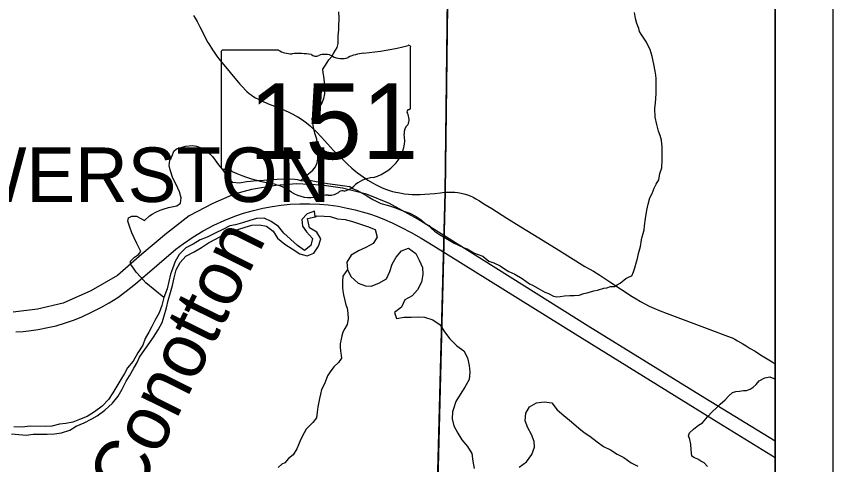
# Model space of a CAD drawing. Extents: x -1.2 to 34, y -8.5 to 22.
# Drawn here: x 7.582 to 9, y 16.749 to 17.528 of the extents above; entities that cross this region are included whole.
import ezdxf

# ---------------------------------------------------------------- set-up
doc = ezdxf.new("R2010")
doc.units = 0
for name, color, linetype in [('GM_X_Corporation_Text', 7, 'Continuous'), ('GM_X_Major_River', 7, 'Continuous'), ('GM_X_Major_River_Text', 7, 'Continuous'), ('GM_X_Minor_River', 7, 'Continuous'), ('GM_X_Rail_Line', 7, 'Continuous'), ('GM_X_State_Location', 7, 'Continuous'), ('GM_X_State_Route', 7, 'Continuous'), ('GM_X_State_Shield', 7, 'Continuous'), ('GM_X_Unincorporated_Text', 7, 'Continuous'), ('SH_Cut_Line', 7, 'Continuous'), ('SH_Data', 7, 'Continuous')]:
    doc.layers.add(name, color=color, linetype=linetype)

msp = doc.modelspace()

# ---------------------------------------------------------------- linework, layer by layer
at = {"layer": 'GM_X_Major_River'}
for points in [[(7.5731, 16.8023), (7.5861, 16.801), (7.5986, 16.8), (7.6107, 16.8013), (7.6233, 16.8018), (7.6354, 16.8016), (7.6479, 16.8021), (7.6604, 16.8041), (7.6744, 16.8085), (7.6857, 16.8154), (7.6993, 16.8213), (7.7126, 16.8283), (7.7224, 16.8337), (7.7352, 16.843), (7.7487, 16.8553), (7.7588, 16.8676), (7.7655, 16.8798), (7.7725, 16.8935), (7.7781, 16.9031), (7.7859, 16.9161), (7.7915, 16.926), (7.7959, 16.9355), (7.8049, 16.9489), (7.8135, 16.9608), (7.8198, 16.9704), (7.828, 16.983), (7.8351, 16.9956), (7.8384, 17.0074), (7.8424, 17.0211), (7.8452, 17.034), (7.8493, 17.0477), (7.8529, 17.0599), (7.8562, 17.0733), (7.8594, 17.087), (7.8661, 17.0999), (7.8762, 17.1111), (7.8906, 17.1185), (7.9034, 17.1258), (7.9154, 17.1339), (7.9279, 17.1405), (7.9418, 17.1483), (7.9535, 17.1537), (7.9664, 17.1573), (7.9793, 17.1616), (7.991, 17.1648), (8.0043, 17.1654), (8.0165, 17.1632), (8.028, 17.1546), (8.0357, 17.1422), (8.0484, 17.1317), (8.061, 17.1239), (8.074, 17.115), (8.087, 17.1117), (8.0983, 17.1164), (8.1065, 17.1283), (8.1109, 17.1412), (8.1035, 17.1529), (8.0909, 17.1603), (8.0876, 17.1766)], [(8.1009, 17.1794), (8.0997, 17.1893), (8.0868, 17.1846), (8.0779, 17.1749), (8.079, 17.1634), (8.0857, 17.1531), (8.0965, 17.1418), (8.0936, 17.1293), (8.0823, 17.1208), (8.0704, 17.1294), (8.0466, 17.1511), (8.037, 17.1623), (8.0247, 17.1713), (8.0121, 17.1772), (7.9992, 17.1763), (7.9875, 17.1731), (7.9746, 17.1688), (7.9625, 17.1652), (7.9527, 17.1636), (7.9402, 17.1574), (7.9274, 17.1508), (7.913, 17.1438), (7.9013, 17.1391), (7.8889, 17.1321), (7.876, 17.1255), (7.8648, 17.114), (7.8577, 17.1017), (7.8529, 17.0892), (7.8493, 17.0796), (7.8467, 17.0671), (7.8435, 17.0541), (7.838, 17.0389), (7.8347, 17.0252), (7.8299, 17.0126), (7.8225, 16.9992), (7.8169, 16.9885), (7.8121, 16.9786), (7.8054, 16.9679), (7.8014, 16.9561), (7.7928, 16.9427), (7.7846, 16.9286), (7.7749, 16.9167), (7.7697, 16.9068), (7.763, 16.8968), (7.7563, 16.885), (7.7496, 16.8735), (7.7421, 16.8617), (7.7309, 16.8501), (7.7177, 16.8405), (7.7045, 16.8324), (7.6913, 16.8269), (7.6796, 16.8222), (7.6678, 16.8202), (7.6565, 16.8189), (7.6432, 16.8157), (7.6315, 16.8148), (7.6056, 16.8152), (7.592, 16.8136), (7.5775, 16.8141)], [(8.0876, 17.1766), (8.1009, 17.1794)], [(8.1009, 17.1794), (8.1036, 17.181), (8.1165, 17.1804), (8.1268, 17.1801), (8.1397, 17.1761), (8.153, 17.1748), (8.166, 17.1711), (8.1778, 17.1671), (8.1919, 17.1627), (8.2049, 17.1572), (8.2088, 17.1439), (8.2014, 17.1332), (8.1889, 17.1259), (8.1761, 17.12), (8.1636, 17.113), (8.1558, 17.1004), (8.1571, 17.0879), (8.163, 17.0754), (8.1756, 17.0642), (8.1886, 17.0594), (8.1981, 17.0588), (8.2117, 17.0639), (8.2249, 17.0713), (8.2304, 17.0842), (8.2345, 17.0968), (8.2419, 17.109), (8.2509, 17.1202), (8.263, 17.1249), (8.2756, 17.1159), (8.2815, 17.1038), (8.2873, 17.091), (8.2878, 17.0792), (8.2854, 17.0656), (8.2787, 17.0526), (8.2697, 17.0418), (8.2569, 17.0352), (8.2506, 17.0226), (8.2385, 17.013), (8.2421, 17.0024), (8.2557, 17.0049), (8.2675, 17.005), (8.2811, 17.0055), (8.291, 17.0049), (8.3051, 17.0005), (8.3178, 16.9916), (8.3255, 16.9795), (8.3351, 16.9671), (8.3471, 16.9551), (8.3589, 16.9462), (8.3655, 16.9345), (8.3687, 16.9212), (8.3696, 16.9091), (8.3687, 16.8966), (8.3612, 16.8832), (8.353, 16.8706), (8.3452, 16.8583), (8.3412, 16.8454)], [(8.4556, 16.744), (8.468, 16.7536), (8.4773, 16.7662), (8.4821, 16.7792), (8.4816, 16.7887), (8.4769, 16.8007), (8.4703, 16.8128), (8.466, 16.8245), (8.467, 16.8378), (8.4733, 16.8493), (8.4857, 16.8563), (8.4986, 16.8579), (8.5119, 16.8558), (8.5212, 16.8438), (8.5327, 16.8341), (8.5461, 16.8232), (8.5588, 16.812), (8.5684, 16.8045), (8.5779, 16.7982), (8.591, 16.7881), (8.6021, 16.7799), (8.6139, 16.7743), (8.6258, 16.7669), (8.6373, 16.761), (8.6499, 16.752), (8.6614, 16.7457)], [(8.3412, 16.8454), (8.3397, 16.8404), (8.3387, 16.8283), (8.3419, 16.8162), (8.3489, 16.8034), (8.3555, 16.7917), (8.3655, 16.78), (8.3729, 16.768), (8.3746, 16.7544), (8.3774, 16.7419)]]:
    msp.add_lwpolyline(points, dxfattribs=at)
at = {"layer": 'GM_X_Minor_River'}
for points in [[(8.0755, 17.2425), (8.0968, 17.2604), (8.1017, 17.2665), (8.1042, 17.2734), (8.1057, 17.2803), (8.1054, 17.2982), (8.1045, 17.3092), (8.1037, 17.3146), (8.1021, 17.3195), (8.1005, 17.3248), (8.0977, 17.3354), (8.096, 17.3445), (8.0956, 17.3502), (8.0978, 17.3556), (8.1011, 17.3606), (8.1089, 17.3714), (8.1126, 17.3764), (8.1159, 17.3852), (8.1177, 17.3932), (8.1183, 17.4032), (8.117, 17.4134), (8.1157, 17.4241), (8.1149, 17.4294), (8.1144, 17.4359), (8.1174, 17.4412), (8.1218, 17.4474), (8.1248, 17.4524), (8.1296, 17.4582), (8.1333, 17.4643), (8.1389, 17.4739), (8.1407, 17.4804), (8.1406, 17.4888), (8.1409, 17.4938), (8.1418, 17.5044), (8.1418, 17.5102), (8.1423, 17.525), (8.1422, 17.5357)], [(8.3085, 17.1546), (8.3169, 17.1487), (8.328, 17.1424), (8.3425, 17.1338), (8.3486, 17.1309), (8.36, 17.1253), (8.365, 17.1235), (8.3764, 17.1168), (8.3821, 17.1146), (8.3924, 17.111), (8.4027, 17.1024), (8.4115, 17.0995), (8.4222, 17.0939), (8.4317, 17.088), (8.4374, 17.0846), (8.4477, 17.0794), (8.4607, 17.0724), (8.4733, 17.0627), (8.4787, 17.0605), (8.4875, 17.0553), (8.5, 17.0482), (8.5065, 17.046), (8.5149, 17.0416), (8.521, 17.0402), (8.5263, 17.041), (8.5338, 17.0419), (8.5433, 17.0424), (8.5509, 17.0425), (8.5596, 17.0434), (8.5679, 17.0462), (8.5735, 17.0474), (8.5852, 17.0507), (8.5912, 17.0519), (8.6022, 17.0551), (8.6075, 17.056), (8.6139, 17.058), (8.6207, 17.0584), (8.6256, 17.0612), (8.6308, 17.0639), (8.6405, 17.0721), (8.6462, 17.0748), (8.6511, 17.0768), (8.654, 17.0837), (8.6562, 17.0906), (8.6591, 17.1009), (8.6609, 17.107), (8.6626, 17.1158), (8.6659, 17.1277), (8.668, 17.1395), (8.669, 17.1445), (8.6709, 17.1506), (8.6723, 17.1567), (8.6729, 17.1636), (8.675, 17.1762), (8.6771, 17.1907), (8.6796, 17.2014), (8.6825, 17.2125), (8.6865, 17.2202), (8.6898, 17.229), (8.6935, 17.2359), (8.6979, 17.2439), (8.6997, 17.2546), (8.7029, 17.2646), (8.7035, 17.2787), (8.7037, 17.2874), (8.7039, 17.3004), (8.7026, 17.3126), (8.7002, 17.3209), (8.6975, 17.3285), (8.6943, 17.3399), (8.6918, 17.3528), (8.6912, 17.3676), (8.6919, 17.3775), (8.6932, 17.3932), (8.6936, 17.4145), (8.6935, 17.4198), (8.6927, 17.4255), (8.6915, 17.4324), (8.6894, 17.4445), (8.6866, 17.4582), (8.683, 17.4703), (8.6803, 17.4753), (8.6764, 17.4828), (8.6709, 17.4915), (8.6671, 17.4968), (8.6644, 17.5017), (8.6632, 17.5066), (8.6596, 17.5153), (8.6576, 17.5244), (8.6556, 17.5343)], [(7.8046, 17.1728), (7.8129, 17.1811), (7.8178, 17.1838), (7.8242, 17.1877), (7.8313, 17.1909), (7.8366, 17.1925), (7.846, 17.1953), (7.8547, 17.1973), (7.8603, 17.1985), (7.8667, 17.2032), (7.8681, 17.2124), (7.8653, 17.2226), (7.8591, 17.2355), (7.8536, 17.2464), (7.8489, 17.2608), (7.8472, 17.2688), (7.8486, 17.278), (7.8527, 17.2853), (7.8552, 17.2933), (7.8601, 17.2976), (7.8699, 17.3004), (7.8755, 17.302), (7.882, 17.3028), (7.888, 17.3033), (7.8948, 17.3023), (7.9043, 17.299), (7.9105, 17.2953), (7.9177, 17.2889), (7.9227, 17.2844), (7.927, 17.278), (7.9328, 17.2697), (7.9386, 17.2626), (7.9436, 17.2562), (7.9471, 17.2505), (7.9502, 17.2456), (7.9571, 17.2396), (7.9692, 17.2383), (7.9817, 17.2407), (7.9888, 17.2416), (7.9938, 17.2421), (8.0017, 17.2426), (8.021, 17.2436), (8.035, 17.2446), (8.0584, 17.2453), (8.0653, 17.245), (8.0702, 17.2444), (8.0755, 17.2425), (8.0816, 17.2422), (8.0869, 17.2431), (8.0941, 17.2428), (8.1028, 17.2407), (8.1161, 17.2382), (8.1222, 17.2371), (8.1442, 17.2344), (8.1525, 17.2334), (8.1609, 17.232), (8.167, 17.2279), (8.1734, 17.2257), (8.1826, 17.2205), (8.1906, 17.2157), (8.2013, 17.2094), (8.2147, 17.2027), (8.2283, 17.1988), (8.2386, 17.1955), (8.2504, 17.1907), (8.2565, 17.1889), (8.2656, 17.1856), (8.2763, 17.1801), (8.2851, 17.1741), (8.292, 17.1677), (8.2981, 17.1644), (8.3023, 17.1595), (8.3085, 17.1546)], [(7.838, 17.0389), (7.8066, 17.0648), (7.7978, 17.0746), (7.7901, 17.0832), (7.7839, 17.0919), (7.78, 17.0972), (7.7803, 17.1025), (7.787, 17.1091), (7.7938, 17.1138), (7.7979, 17.1192), (7.794, 17.1271), (7.7909, 17.1331), (7.7862, 17.1426), (7.7823, 17.1517), (7.7783, 17.163), (7.7752, 17.1721), (7.7766, 17.1779), (7.7826, 17.1806), (7.7906, 17.1804), (7.799, 17.1759), (7.8045, 17.1729)], [(8.1571, 17.0879), (8.1487, 17.0761), (8.1481, 17.0673), (8.1486, 17.0566), (8.1487, 17.0505), (8.1499, 17.0437), (8.1523, 17.0342), (8.1543, 17.0266), (8.1563, 17.0206), (8.1576, 17.0118), (8.1581, 17.0019), (8.1567, 16.992), (8.1526, 16.9855), (8.1489, 16.9786), (8.1475, 16.9725), (8.1461, 16.9667), (8.1443, 16.9587), (8.1444, 16.9534), (8.1449, 16.9458), (8.1461, 16.9386), (8.1466, 16.9336), (8.1414, 16.9263), (8.1335, 16.9186), (8.1272, 16.9101), (8.1224, 16.9028), (8.1202, 16.8963), (8.1169, 16.889), (8.1121, 16.8794), (8.11, 16.871), (8.1082, 16.8637), (8.1071, 16.8576), (8.1054, 16.8488), (8.1044, 16.8397), (8.103, 16.8301), (8.0971, 16.8221), (8.0922, 16.8174), (8.0851, 16.8104), (8.0818, 16.8039), (8.0759, 16.7928), (8.0722, 16.7828), (8.0689, 16.7759), (8.0627, 16.7656), (8.0548, 16.759), (8.0481, 16.752), (8.0428, 16.7493), (8.0368, 16.7438)], [(8.7823, 16.7456), (8.7765, 16.752), (8.7708, 16.7549), (8.7658, 16.7579), (8.7601, 16.7605), (8.7552, 16.7635), (8.7539, 16.7745), (8.7537, 16.784), (8.7517, 16.7924), (8.7497, 16.7984), (8.7515, 16.8038), (8.7583, 16.8103), (8.7669, 16.8173), (8.774, 16.8212), (8.7826, 16.8317), (8.7904, 16.8402), (8.7986, 16.8479), (8.8046, 16.8537), (8.8132, 16.8611), (8.8188, 16.8676), (8.8259, 16.8742), (8.8315, 16.8758), (8.8383, 16.8763), (8.8448, 16.8772), (8.8501, 16.8776), (8.8565, 16.88), (8.8621, 16.8835), (8.8673, 16.8878), (8.8722, 16.8943), (8.8819, 16.8994), (8.891, 16.9015), (8.8975, 16.8981), (8.9, 16.8969)]]:
    msp.add_lwpolyline(points, dxfattribs=at)
at = {"layer": 'GM_X_Rail_Line'}
for points in [[(8.9, 16.7891), (8.7777, 16.8641), (8.5752, 16.9893), (8.279, 17.1752), (8.2298, 17.2027), (8.19, 17.2185), (8.1486, 17.2291), (8.1119, 17.2345), (8.069, 17.2365), (8.0325, 17.2336), (7.9904, 17.2271), (7.9601, 17.2186), (7.9229, 17.2028), (7.8818, 17.181), (7.8424, 17.1504), (7.8, 17.1143), (7.7574, 17.0774), (7.7113, 17.0509), (7.6629, 17.0294), (7.6185, 17.0188), (7.5763, 17.0139)], [(7.581, 16.9792), (7.5935, 16.9801), (7.6077, 16.9815), (7.6196, 16.9834), (7.6363, 16.987), (7.6507, 16.9901), (7.6674, 16.9952), (7.6809, 16.9997), (7.6943, 17.005), (7.7123, 17.0134), (7.7286, 17.0215), (7.743, 17.03), (7.758, 17.0394), (7.7728, 17.0504), (7.7887, 17.0631), (7.8296, 17.0983), (7.8587, 17.123), (7.8718, 17.1327), (7.8884, 17.144), (7.9062, 17.1548), (7.9246, 17.165), (7.9427, 17.1729), (7.9611, 17.1804), (7.9764, 17.1855), (7.9936, 17.1904), (8.0098, 17.1944), (8.0259, 17.1976), (8.0417, 17.1997), (8.0576, 17.2012), (8.0741, 17.2018), (8.0915, 17.202), (8.1092, 17.2013), (8.1237, 17.2001), (8.1407, 17.1977), (8.1567, 17.1945), (8.1703, 17.1915), (8.1826, 17.1881), (8.1952, 17.1845), (8.2084, 17.1797), (8.2214, 17.1745), (8.2348, 17.1688), (8.2498, 17.1615), (8.2674, 17.1521), (8.2848, 17.1422), (8.306, 17.1295), (8.5527, 16.9762), (8.8022, 16.8214), (8.9, 16.7607)]]:
    msp.add_lwpolyline(points, dxfattribs=at)
at = {"layer": 'GM_X_State_Route'}
for points in [[(7.8894, 17.5293), (7.8924, 17.5246), (7.8958, 17.5188), (7.9007, 17.5096), (7.9146, 17.4827), (7.9162, 17.4799), (7.9227, 17.4694), (7.9252, 17.4655), (7.9301, 17.4585), (7.9337, 17.4539), (7.9534, 17.43), (7.9701, 17.4102), (7.975, 17.4045), (7.9796, 17.3996), (7.9824, 17.397), (7.9862, 17.3937), (7.9896, 17.3912), (7.9928, 17.3891), (7.9975, 17.3862), (8.0022, 17.3837), (8.0065, 17.3817), (8.0209, 17.3755), (8.03, 17.3719), (8.0476, 17.3646), (8.0562, 17.3608), (8.0598, 17.3591), (8.0697, 17.3537), (8.0754, 17.3502), (8.0812, 17.3464), (8.0856, 17.343), (8.0924, 17.3373), (8.0965, 17.3336), (8.1025, 17.3275), (8.1116, 17.3176), (8.133, 17.2946), (8.1373, 17.2902), (8.1505, 17.2771), (8.1573, 17.2707), (8.1645, 17.2642), (8.1717, 17.2581), (8.1745, 17.256), (8.1902, 17.2448), (8.1926, 17.2432), (8.2014, 17.2377), (8.2055, 17.2354), (8.2124, 17.2318), (8.2174, 17.2295), (8.2249, 17.2266), (8.23, 17.225), (8.235, 17.2236), (8.2412, 17.2222), (8.248, 17.2209), (8.2562, 17.2196), (8.2633, 17.2188), (8.2697, 17.2183), (8.2768, 17.2181), (8.2833, 17.2182), (8.2916, 17.2186), (8.3087, 17.2202), (8.3189, 17.2213), (8.3257, 17.222), (8.3328, 17.2224)], [(8.3328, 17.2224), (8.3433, 17.2222), (8.3487, 17.2216), (8.3547, 17.2206), (8.3591, 17.2194), (8.3653, 17.2176), (8.3703, 17.2156), (8.3755, 17.2133), (8.3802, 17.2108), (8.3863, 17.2072), (8.3942, 17.2022), (8.4076, 17.1936), (8.4338, 17.1772), (8.458, 17.1622), (8.4788, 17.1494), (8.5044, 17.1335), (8.524, 17.1213), (8.5696, 17.0933), (8.5843, 17.0847), (8.5954, 17.0777), (8.613, 17.0662), (8.6519, 17.0408), (8.6584, 17.037), (8.6662, 17.0322), (8.6738, 17.028), (8.681, 17.0243), (8.6891, 17.0206), (8.7004, 17.0159), (8.7126, 17.0111), (8.7589, 16.9937), (8.7868, 16.9833), (8.8175, 16.9721), (8.8252, 16.9689), (8.8299, 16.9665), (8.8349, 16.9639), (8.8438, 16.9586), (8.8496, 16.9551), (8.8569, 16.9507), (8.8651, 16.9457), (8.8748, 16.9397), (8.8946, 16.9271), (8.9, 16.9238)]]:
    msp.add_lwpolyline(points, dxfattribs=at)
at = {"layer": 'GM_X_State_Shield'}
for p, q in [((8.2668, 17.3695), (8.2668, 17.4741)), ((7.9373, 17.4657), (7.9373, 17.2656)), ((8.037, 17.4692), (7.9405, 17.4692)), ((8.2668, 17.3695), (8.2668, 17.3695))]:
    msp.add_line(p, q, dxfattribs=at)
for centre, major_axis, start_param, end_param in [((8.1494, 17.742), (0.3495, 0), 4.814394, 5.042369), ((8.2632, 17.4746), (0.00367, 0), 6.141152, 7.989035), ((7.941, 17.4662), (0.00382, 0), 1.712693, 3.28349), ((8.06, 17.4924), (0.037, 0), 4.042523, 4.731795), ((8.0723, 17.3568), (0.133, 0), 1.404758, 1.657858), ((8.1025, 17.4672), (0.0107, 0), 3.836095, 5.185415), ((8.1182, 17.4441), (0.0222, 0), 0.950623, 2.079405), ((8.194, 17.4081), (0.0703, 0), 1.699011, 2.107814), ((8.1468, 17.4758), (0.0267, 0), 4.081561, 5.145723), ((8.266, 17.3618), (0.00568, 0), 1.883978, 3.671073), ((8.2629, 17.369), (0.00393, 0), 5.05454, 6.418171), ((8.2299, 17.3485), (0.0341, 0), 5.934695, 6.695948), ((8.28, 17.3256), (0.0248, 0), 2.387724, 3.262537), ((8.169, 17.3123), (0.0874, 0), 5.101752, 6.440018), ((7.9411, 17.2652), (0.00385, 0), 3.00124, 4.508301), ((7.9417, 17.2857), (0.0294, 0), 4.665946, 4.897461), ((7.9477, 17.2541), (0.0106, 0), 0.519207, 1.627899), ((8.0815, 17.4339), (0.2524, 0), 4.195997, 4.488961), ((8.2059, 17.2094), (0.0479, 0), 1.647645, 2.488434), ((8.0062, 17.1757), (0.079, 0), 0.823519, 1.323587), ((8.1452, 17.2462), (0.0282, 0), 4.937069, 5.64225), ((8.0917, 17.2531), (0.0501, 0), 4.026481, 4.996735), ((8.1243, 17.2381), (0.0267, 0), 4.691044, 5.507374), ((8.1484, 17.2187), (0.00752, 0), 1.147584, 2.315152), ((8.1206, 17.1839), (0.0412, 0), 1.495662, 1.94098)]:
    msp.add_ellipse(centre, major_axis=major_axis, ratio=0.8, start_param=start_param, end_param=end_param, dxfattribs=at)
at = {"layer": 'GM_X_Unincorporated_Text'}
for p, q in [((8.3265, 17.2224), (8.3326, 17.6871)), ((8.3029, 16.2873), (8.3265, 17.2224))]:
    msp.add_line(p, q, dxfattribs=at)
msp.add_lwpolyline([(8.2551, 14.1), (8.9, 14.1), (8.9, 17.6758), (8.3326, 17.6871), (8.3265, 17.2224), (8.3029, 16.2873), (8.2955, 15.9378), (8.2794, 15.1757), (8.2772, 15.0742)], close=True, dxfattribs=at)
at = {"layer": 'SH_Cut_Line'}
msp.add_lwpolyline([(2.3586, 14.1), (8.9, 14.1), (8.9, 17.6758), (8.3326, 17.6871), (7.9782, 17.6941), (7.8111, 17.6977), (7.3722, 17.707), (7.1254, 17.7122), (6.7322, 17.7204), (6.6751, 17.7216), (6.665, 17.7216)], dxfattribs=at)
at = {"layer": 'SH_Data'}
for p, q in [((9, 21), (9, 14)), ((9, 21), (9, 14)), ((8.9, 20.9), (8.9, 14.1)), ((8.9, 20.9), (8.9, 14.1))]:
    msp.add_line(p, q, dxfattribs=at)

# ---------------------------------------------------------------- texts
at = {"layer": 'GM_X_Corporation_Text'}
msp.add_text('BOWERSTON', height=0.0947, rotation=0, dxfattribs=at).set_placement((7.2968, 17.2052))
at = {"layer": 'GM_X_Major_River_Text'}
msp.add_text('Conotton', height=0.09472, rotation=63.5646, dxfattribs=at).set_placement((7.7875, 16.6807))
at = {"layer": 'GM_X_State_Location'}
for s in ['s', 'r']:
    msp.add_text(s, height=0.000189, dxfattribs=at).set_placement((8.0983, 17.3524))
msp.add_text('151', height=0.000189, rotation=0, dxfattribs=at).set_placement((8.0315, 17.3386))
at = {"layer": 'GM_X_State_Shield'}
msp.add_text('151', height=0.13184, dxfattribs=at).set_placement((7.9858, 17.2797))

doc.saveas('drawing.dxf')
